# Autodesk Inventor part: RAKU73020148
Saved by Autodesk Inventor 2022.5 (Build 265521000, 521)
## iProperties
Created: 2024-11
Part Number: RAKU73020148
Material: Generic
Description: NOT SPECIFIED
Document SubType Name: Modeling
Designer: AdminForWorker
Density: 1 g/cm^3
Appearance: Default
Title: RAKU73020148
Author: AdminForWorker
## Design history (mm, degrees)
feature "Body1"
body "Solid1"
